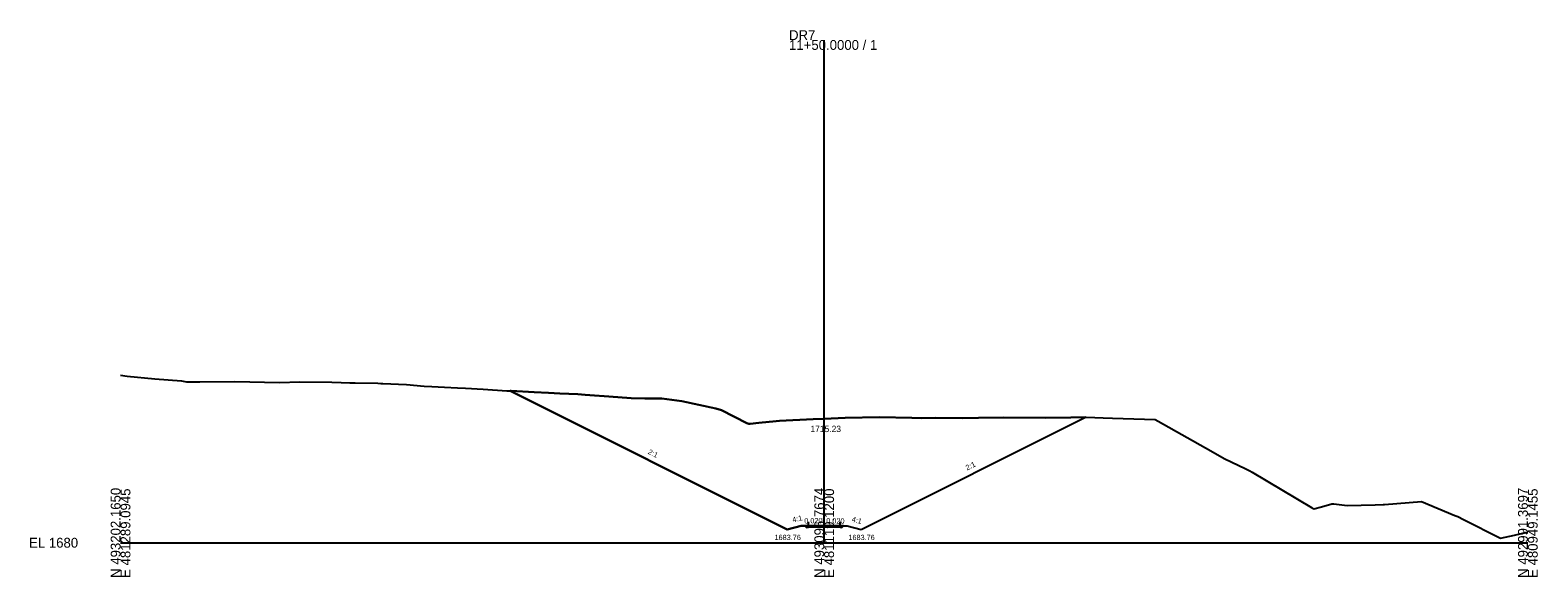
# Model space of a CAD drawing. Extents: x -26 to 403, y -10 to 4215.
# Drawn here: x -25.7 to 402.8, y 1490.3 to 1645.6 of the extents above; entities that cross this region are included whole.
import ezdxf

# ---------------------------------------------------------------- set-up
doc = ezdxf.new("R2010")
doc.units = 0
for name, color, linetype in [('Exist Cross Section Cell', 7, 'Continuous'), ('Exist XS Center Line Elevation Label', 7, 'Continuous'), ('Exist XS Ground Line', 7, 'Continuous'), ('Prop XS Ditch Slope Text', 7, 'Continuous'), ('Prop XS Ditch Standard Text', 7, 'Continuous'), ('Prop XS Dump Level', 7, 'Continuous'), ('Prop XS Earthwork Shape', 7, 'Continuous'), ('Prop XS EOT Tick Mark', 7, 'Continuous'), ('Prop XS Finish Grade', 7, 'Continuous'), ('Prop XS Finish Grade Earthwork', 7, 'Continuous'), ('Prop XS Finish Grade Pavement', 7, 'Continuous'), ('Prop XS Hydro Typical Ditch Data', 7, 'Continuous'), ('Prop XS Pvmt Edge Slope', 7, 'Continuous'), ('Prop XS SE Text', 7, 'Continuous'), ('Prop XS Shoulder Borrow Shape', 7, 'Continuous'), ('Prop XS Side Slope Text', 7, 'Continuous'), ('Prop XS Subgrade Earthwork', 7, 'Continuous')]:
    doc.layers.add(name, color=color, linetype=linetype)

msp = doc.modelspace()

# ---------------------------------------------------------------- linework, layer by layer
at = {"layer": 'Exist Cross Section Cell'}
for p, q in [((200, 1500), (200, 1642.82)), ((0, 1500), (200, 1500)), ((200, 1500), (400, 1500))]:
    msp.add_line(p, q, dxfattribs=at)
at = {"layer": 'Exist XS Ground Line'}
msp.add_lwpolyline([(0, 1547.61), (1.86, 1547.35), (9.77, 1546.58), (17.34, 1546.03), (18.75, 1545.73), (19.73, 1545.73), (21.11, 1545.72), (22.56, 1545.72), (32.53, 1545.79), (45.17, 1545.53), (50.99, 1545.69), (60.06, 1545.57), (62.75, 1545.48), (65.2, 1545.46), (66.71, 1545.39), (73.09, 1545.32), (73.97, 1545.28), (74.52, 1545.27), (81.24, 1544.94), (86.29, 1544.52), (88.5, 1544.4), (92.07, 1544.2), (95.77, 1543.97), (98.06, 1543.9), (103.03, 1543.6), (109.83, 1543.17), (110.29, 1543.15), (111.04, 1543.12), (117.56, 1542.78), (121.6, 1542.57), (124.82, 1542.43), (130.02, 1542.18), (132.09, 1542.06), (133.37, 1541.93), (138.82, 1541.52), (145.14, 1541.04), (149, 1540.98), (153.88, 1541), (159.56, 1540.18), (169.16, 1538.11), (170.79, 1537.65), (178, 1533.98), (178.57, 1533.76), (179, 1533.82), (181.4, 1534.05), (186.36, 1534.55), (187.33, 1534.64), (196.85, 1535.07), (200, 1535.23), (203.98, 1535.42), (205.94, 1535.44), (215.75, 1535.64), (224.92, 1535.47), (227.52, 1535.43), (231.75, 1535.44), (239.29, 1535.42), (243.9, 1535.5), (251.05, 1535.55), (262.88, 1535.51), (270.11, 1535.6), (274.59, 1535.63), (279.33, 1535.48), (281.97, 1535.38), (294.1, 1535), (294.95, 1534.54), (309.9, 1526.06), (313.7, 1523.91), (319.82, 1520.97), (320.96, 1520.43), (321.67, 1520.08), (338.48, 1509.98), (339.13, 1509.59), (341.32, 1510.18), (344.29, 1511.06), (344.9, 1511.04), (348.66, 1510.56), (356.57, 1510.74), (358.84, 1510.85), (359.26, 1510.88), (369.76, 1511.67), (379.23, 1507.75), (380.06, 1507.41), (381.74, 1506.56), (392.21, 1501.29), (396.25, 1502.11), (398.24, 1502.6), (399.41, 1502.89), (400, 1502.86)], dxfattribs=at)
at = {"layer": 'Prop XS Dump Level'}
for p, q in [((195.5, 1504.92), (200, 1505.01)), ((200, 1505.01), (204.5, 1504.92))]:
    msp.add_line(p, q, dxfattribs=at)
at = {"layer": 'Prop XS Earthwork Shape'}
msp.add_lwpolyline([(210.5, 1503.76), (274.23, 1535.63), (270.11, 1535.6), (262.88, 1535.51), (251.05, 1535.55), (243.9, 1535.5), (239.29, 1535.42), (231.75, 1535.44), (227.52, 1535.43), (224.92, 1535.47), (215.75, 1535.64), (205.94, 1535.44), (203.98, 1535.42), (200, 1535.23), (196.85, 1535.07), (187.33, 1534.64), (186.36, 1534.55), (181.4, 1534.05), (179, 1533.82), (178.57, 1533.76), (178, 1533.98), (170.79, 1537.65), (169.16, 1538.11), (159.56, 1540.18), (153.88, 1541), (149, 1540.98), (145.14, 1541.04), (138.82, 1541.52), (133.37, 1541.93), (132.09, 1542.06), (130.02, 1542.18), (124.82, 1542.43), (121.6, 1542.57), (117.56, 1542.78), (111.04, 1543.12), (110.77, 1543.13), (189.5, 1503.76), (193.5, 1504.76), (194.48, 1504.84), (194.95, 1504.37), (195.5, 1504.38), (200, 1504.47), (204.5, 1504.38), (205.05, 1504.37), (205.52, 1504.84), (206.5, 1504.76)], close=True, dxfattribs=at)
at = {"layer": 'Prop XS EOT Tick Mark'}
for p, q in [((195.5, 1504.92), (195.5, 1505.92)), ((204.5, 1504.92), (204.5, 1505.92))]:
    msp.add_line(p, q, dxfattribs=at)
at = {"layer": 'Prop XS Finish Grade'}
for p, q in [((195.5, 1504.92), (194.48, 1504.84)), ((204.5, 1504.92), (205.52, 1504.84))]:
    msp.add_line(p, q, dxfattribs=at)
at = {"layer": 'Prop XS Finish Grade Earthwork'}
for p, q in [((189.5, 1503.76), (110.77, 1543.13)), ((210.5, 1503.76), (274.23, 1535.63)), ((193.5, 1504.76), (189.5, 1503.76)), ((194.48, 1504.84), (193.5, 1504.76)), ((205.52, 1504.84), (206.5, 1504.76)), ((206.5, 1504.76), (210.5, 1503.76))]:
    msp.add_line(p, q, dxfattribs=at)
at = {"layer": 'Prop XS Finish Grade Pavement'}
for p, q in [((195.5, 1504.92), (200, 1505.01)), ((200, 1505.01), (204.5, 1504.92))]:
    msp.add_line(p, q, dxfattribs=at)
at = {"layer": 'Prop XS Hydro Typical Ditch Data'}
for p, q in [((189.5, 1503.76), (110.77, 1543.13)), ((210.5, 1503.76), (274.23, 1535.63)), ((193.5, 1504.76), (189.5, 1503.76)), ((206.5, 1504.76), (210.5, 1503.76))]:
    msp.add_line(p, q, dxfattribs=at)
at = {"layer": 'Prop XS Pvmt Edge Slope'}
for p, q in [((195.5, 1504.92), (194.95, 1504.37)), ((204.5, 1504.92), (205.05, 1504.37))]:
    msp.add_line(p, q, dxfattribs=at)
at = {"layer": 'Prop XS Shoulder Borrow Shape'}
for points in [[(195.5, 1504.92), (194.95, 1504.37), (194.48, 1504.84)], [(195.5, 1504.92), (194.95, 1504.37), (194.48, 1504.84)], [(205.05, 1504.37), (205.52, 1504.84), (204.5, 1504.92)], [(205.05, 1504.37), (205.52, 1504.84), (204.5, 1504.92)]]:
    msp.add_lwpolyline(points, close=True, dxfattribs=at)
at = {"layer": 'Prop XS Subgrade Earthwork'}
for p, q in [((194.95, 1504.37), (194.48, 1504.84)), ((195.5, 1504.38), (194.95, 1504.37)), ((200, 1504.47), (195.5, 1504.38)), ((204.5, 1504.38), (200, 1504.47)), ((204.5, 1504.38), (205.05, 1504.37)), ((205.05, 1504.37), (205.52, 1504.84))]:
    msp.add_line(p, q, dxfattribs=at)

# ---------------------------------------------------------------- texts
at = {"layer": 'Exist Cross Section Cell'}
for s, p in [('DR7', (190, 1642.82)), ('11+50.0000 / 1', (190, 1640.02)), ('EL 1680', (-26, 1498.6))]:
    msp.add_text(s, height=2.8, dxfattribs=at).set_placement(p)
for s, p in [('N 493202.1650', (0, 1490)), ('E 481289.0945', (2.8, 1490)), ('N 493096.7674', (200, 1490)), ('E 481119.1200', (202.8, 1490)), ('N 492991.3697', (400, 1490)), ('E 480949.1455', (402.8, 1490))]:
    msp.add_text(s, height=2.8, rotation=90, dxfattribs=at).set_placement(p)
at = {"layer": 'Exist XS Center Line Elevation Label'}
msp.add_text('1715.23', height=1.8, dxfattribs=at).set_placement((196.08, 1531.43))
at = {"layer": 'Prop XS Ditch Slope Text'}
for rotation, p in [(14.0362, (191.14, 1505.72)), (345.9638, (207.71, 1506.01))]:
    msp.add_text('4:1', height=1.5, rotation=rotation, dxfattribs=at).set_placement(p)
at = {"layer": 'Prop XS Ditch Standard Text'}
for p in [(185.88, 1500.76), (206.88, 1500.76)]:
    msp.add_text('1683.76', height=1.5, dxfattribs=at).set_placement(p)
at = {"layer": 'Prop XS Dump Level'}
for p in [(193.5, 1504.72), (206.5, 1504.72)]:
    msp.add_text('Case1', height=0.04, dxfattribs=at).set_placement(p)
at = {"layer": 'Prop XS SE Text'}
for rotation, p in [(1.1458, (194.35, 1505.45)), (358.8542, (200.58, 1505.52))]:
    msp.add_text('0.020', height=1.5, rotation=rotation, dxfattribs=at).set_placement(p)
at = {"layer": 'Prop XS Side Slope Text'}
for rotation, p in [(333.4349, (149.74, 1525.32)), (26.5651, (240.63, 1520.51))]:
    msp.add_text('2:1', height=1.5, rotation=rotation, dxfattribs=at).set_placement(p)

doc.saveas('drawing.dxf')
